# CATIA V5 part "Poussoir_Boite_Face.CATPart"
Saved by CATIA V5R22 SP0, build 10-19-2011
Part number: Poussoir_Boite_Face
Bounding box of the stored display mesh (mm): x -88 to 88, y -5 to 0, z -17 to 17
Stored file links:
  D:\CAO_PER_MODIF_2025\CAO_PER_pick&place_2024P\Sous_Ensemble_Boite\Verin\Poussoir\Poussoir_Boite_Face.CATPart
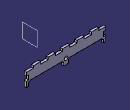
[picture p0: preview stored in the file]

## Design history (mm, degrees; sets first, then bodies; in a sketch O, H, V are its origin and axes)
Body1 (main body)
  Sketch1 on zx-plane, origin (0, 0, 0), H (-1, 0, 0), V (0, 0, 1)
    line L1 (88, -17) -> (83, -17)
    line L2 (-88, -17) -> (-88, 17)
    line L3 (-88, 17) -> (88, 17)
    line L4 (88, 17) -> (88, -17)
    point P5 (-5, -17)
    line L5 (-83, -17) -> (-83, -12)
    line L6 (-78, -7) -> (-10, -7)
    line L7 (-5, -12) -> (-5, -17)
    point P6 (-83, -17)
    point P7 (-83, -7)
    arc A1 centre (-78, -12) radius 5 from (-83, -12) to (-78, -7) cw
    point P8 (-83, -12)
    point P9 (-78, -7)
    arc A2 centre (-10, -12) radius 5 from (-10, -7) to (-5, -12) cw
    point P11 (-10, -7)
    point P12 (-5, -12)
    line L8 (-83, -17) -> (-88, -17)
    point P14 (5, -17)
    point P15 (83, -17)
    point P16 (83, -7)
    point P17 (83, -12)
    point P18 (78, -7)
    point P20 (10, -7)
    point P21 (5, -12)
    line L9 (83, -17) -> (83, -12)
    line L10 (78, -7) -> (10, -7)
    line L11 (5, -12) -> (5, -17)
    arc A3 centre (78, -12) radius 5 from (83, -12) to (78, -7) ccw
    arc A4 centre (10, -12) radius 5 from (10, -7) to (5, -12) ccw
    line L12 (5, -17) -> (-5, -17)
    length L4 = 34
    length L3 = 176
    distance L5 L2 = 5
    distance V L7 = 5
    distance P6 P7 = 10
    radius A1 = 5
    radius A2 = 5
    horizontal: L1 H, L3 H, L6 H, L8 H, L12 H
    vertical: L2 V, L4 V, L5 V, L7 V
    equidistance: L4 L2 O, L1 L3 O
    coincidence: L5 P7, L6 P7, L1 L8, L1 L12
    tangency: A1 L5, A1 L6, A2 L6, A2 L7
    symmetry: P5 P14 V, P6 P15 V, P7 P16 V, P8 P17 V, P9 P18 V, P11 P20 V, P12 P21 V, L5 L9 V, L6 L10 V, L7 L11 V, A1 A3 V, A2 A4 V
  Pad1: profile Sketch1, direction (0, -1, 0), length 5
  Sketch2 on start face of Pad1, origin (-21.5499, 0, 6.2058), H (1, 0, 0), V (0, 0, -1)
    point P1 (21.5499, 11.2058)
    reference projected line E1 (-66.4501, 23.2058) -> (-66.4501, -10.7942) from edge [face of Pad1 from Sketch1.L4 | start face of Pad1]
    reference projected line E2 (109.5499, -10.7942) -> (109.5499, 23.2058) from edge [face of Pad1 from Sketch1.L2 | start face of Pad1]
    reference projected line E3 (-61.4501, 23.2058) -> (-66.4501, 23.2058) from edge [face of Pad1 from Sketch1.L1 | start face of Pad1]
    distance P1 E3 = 12
    equidistance: E1 E2 P1
  Hole1: placed by Sketch2, at (0, 0, -5) direction (0, -1, 0), diameter 8, through (limit type 6)
  Sketch3 on start face of Pad1, origin (0, 0, 0), H (-1, 0, 0), V (0, 0, 1)
    point P1 (-88, 5)
    line L1 (-88, 5) -> (-83, 5)
    line L2 (-83, 5) -> (-83, -5)
    line L3 (-83, -5) -> (-88, -5)
    line L4 (-88, -5) -> (-88, 5)
    point P2 (-83, 5)
    point P3 (-83, -5)
    point P4 (-88, -5)
    reference projected line E1 (-88, 17) -> (-88, -17) from edge [face of Pad1 from Sketch1.L2 | start face of Pad1]
    point P5 (88, 5)
    point P6 (83, 5)
    point P7 (83, -5)
    point P8 (88, -5)
    line L5 (88, 5) -> (83, 5)
    line L6 (83, 5) -> (83, -5)
    line L7 (83, -5) -> (88, -5)
    line L8 (88, -5) -> (88, 5)
    distance L3 L1 = 10
    length L1 = 5
    horizontal: L1 H, L3 H
    vertical: L2 V, L4 V
    coincidence: L4 E1
    equidistance: L3 L1 O
    symmetry: P1 P5 V, P2 P6 V, P3 P7 V, P4 P8 V, L1 L5 V, L2 L6 V, L3 L7 V, L4 L8 V
  Pocket1: profile Sketch3, direction (0, -1, 0), through (limit type 6)
  Sketch4 on start face of Pad1, origin (0, 0, 0), H (-1, 0, 0), V (0, 0, 1)
    point P1 (-24, 17)
    line L1 (-24, 17) -> (-8, 17)
    line L2 (-8, 17) -> (-8, 12)
    line L3 (-8, 12) -> (-24, 12)
    line L4 (-24, 12) -> (-24, 17)
    point P2 (-8, 17)
    point P3 (-8, 12)
    point P4 (-24, 12)
    reference projected line E1 (88, 17) -> (-88, 17) from edge [face of Pad1 from Sketch1.L3 | start face of Pad1]
    point P5 (-40, 17)
    line L5 (-40, 17) -> (-56, 17)
    line L6 (-56, 17) -> (-56, 12)
    line L7 (-56, 12) -> (-40, 12)
    line L8 (-40, 12) -> (-40, 17)
    point P6 (-56, 17)
    point P7 (-56, 12)
    point P8 (-40, 12)
    point P9 (-72, 17)
    line L9 (-72, 17) -> (-88, 17)
    line L10 (-88, 17) -> (-88, 12)
    line L11 (-88, 12) -> (-72, 12)
    line L12 (-72, 12) -> (-72, 17)
    point P10 (-88, 17)
    point P11 (-88, 12)
    point P12 (-72, 12)
    reference projected line E2 (-88, 17) -> (-88, -17) from edge [face of Pad1 from Sketch1.L2 | start face of Pad1]
    point P13 (24, 17)
    point P14 (8, 17)
    point P15 (8, 12)
    point P16 (24, 12)
    point P17 (40, 17)
    point P18 (56, 17)
    point P19 (56, 12)
    point P20 (40, 12)
    point P21 (72, 17)
    point P22 (88, 17)
    point P23 (88, 12)
    point P24 (72, 12)
    line L13 (24, 17) -> (8, 17)
    line L14 (8, 17) -> (8, 12)
    line L15 (8, 12) -> (24, 12)
    line L16 (24, 12) -> (24, 17)
    line L17 (40, 17) -> (56, 17)
    line L18 (56, 17) -> (56, 12)
    line L19 (56, 12) -> (40, 12)
    line L20 (40, 12) -> (40, 17)
    line L21 (72, 17) -> (88, 17)
    line L22 (88, 17) -> (88, 12)
    line L23 (88, 12) -> (72, 12)
    line L24 (72, 12) -> (72, 17)
    length L2 = 5
    length L1 = 16
    distance L4 L8 = 16
    length L5 = 16
    length L9 = 16
    distance L12 L6 = 16
    horizontal: L1 H, L3 H, L5 H, L7 H, L9 H, L11 H
    vertical: L2 V, L4 V, L6 V, L8 V, L10 V, L12 V
    coincidence: L1 E1, P5 L1, L7 L3, P9 L1, P11 L7, L10 E2
    symmetry: P1 P13 V, P2 P14 V, P3 P15 V, P4 P16 V, P5 P17 V, P6 P18 V, P7 P19 V, P8 P20 V, P9 P21 V, P10 P22 V, P11 P23 V, P12 P24 V, L1 L13 V, L2 L14 V, L3 L15 V, L4 L16 V, L5 L17 V, L6 L18 V, L7 L19 V, L8 L20 V, L9 L21 V, L10 L22 V, L11 L23 V, L12 L24 V
  Pocket2: profile Sketch4, direction (0, -1, 0), through (limit type 6)
  DatumSurface1
  Plane1: type Offset, RefPlane DatumSurface1, Offset 88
